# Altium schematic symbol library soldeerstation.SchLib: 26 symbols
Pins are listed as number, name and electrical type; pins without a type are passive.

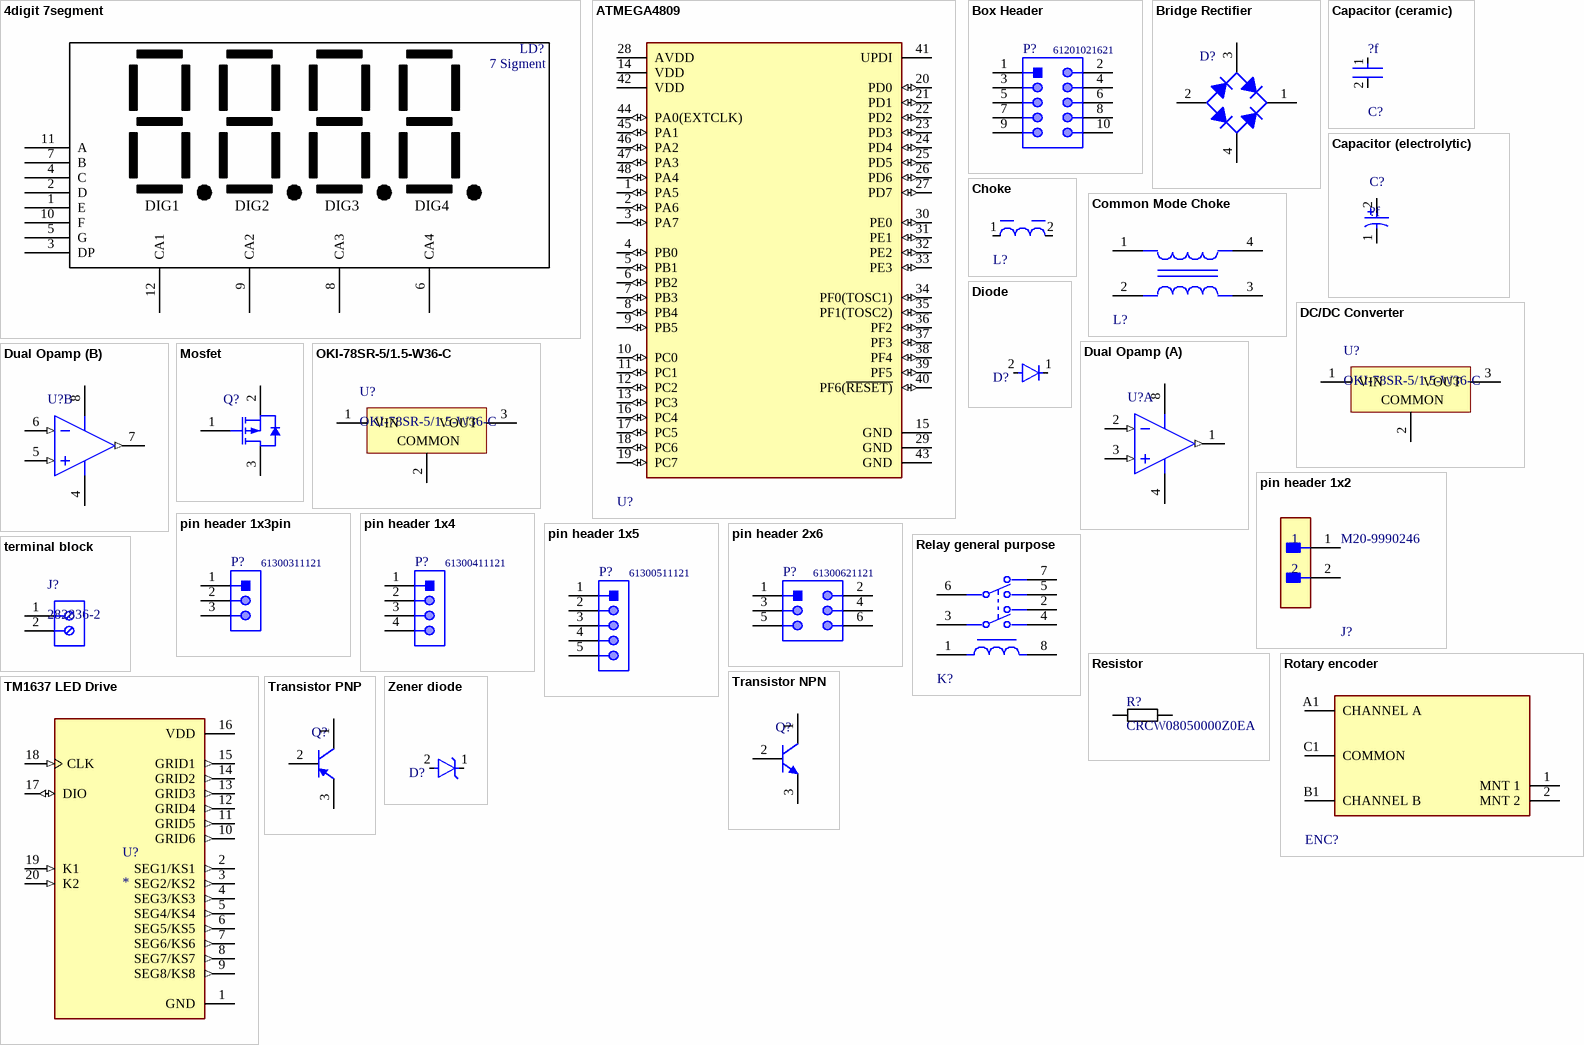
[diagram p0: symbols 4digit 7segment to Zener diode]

## 4digit 7segment
designator LD?, comment 7 Sigment
footprint 7-Segment
pins: 1 E, 2 D, 3 DP, 4 C, 5 G, 6 CA4, 7 B, 8 CA3, 9 CA2, 10 F, 11 A, 12 CA1

## ATMEGA4809
designator U?
Peripherals: Brown-out Detect/Reset; Number of I/Os: 41; Core Architecture: AVR; Memory Size: 48KB; Interface: I2C; Oscillator Type: Internal; Memory Type: FLASH
footprint TQFP_48_L (atmega)
pins: 1 PA5 (io), 2 PA6 (io), 3 PA7 (io), 4 PB0 (io), 5 PB1 (io), 6 PB2 (io), 7 PB3 (io), 8 PB4 (io), 9 PB5 (io), 10 PC0 (io), 11 PC1 (io), 12 PC2 (io), 13 PC3 (io), 14 VDD (power), 15 GND (oe), 16 PC4 (io), 17 PC5 (io), 18 PC6 (io), 19 PC7 (io), 20 PD0 (io), 21 PD1 (io), 22 PD2 (io), 23 PD3 (io), 24 PD4 (io), 25 PD5 (io), 26 PD6 (io), 27 PD7 (io), 28 AVDD (power), 29 GND (power), 30 PE0 (io), 31 PE1 (io), 32 PE2 (io), 33 PE3 (io), 34 PF0(TOSC1) (io), 35 PF1(TOSC2) (io), 36 PF2 (io), 37 PF3 (io), 38 PF4 (io), 39 PF5 (io), 40 PF6(~{RESET)} (io), 41 UPDI, 42 VDD (power), 43 GND (power), 44 PA0(EXTCLK) (io), 45 PA1 (io), 46 PA2 (io), 47 PA3 (io), 48 PA4 (io)

## Box Header
designator P?, comment 61201021621
Male Box Header WR-BHD, THT, Vertical, pitch 2.54 mm, 10 pins; Manufacturer: Wurth Elektronik; Contact Resistance: 20mOhm; Withstanding Voltage: 500VAC; Pin Number: 10; Working Voltage: 250VAC; Pitch: 2.54mm
footprint box header 10-pin (10 pins, straight, gold plating)
pins: 1, 2, 3, 4, 5, 6, 7, 8, 9, 10

## Bridge Rectifier
designator D?
Manufacturer: Diodes Inc; Average Rectified Current-Max: 0.8A; Reverse Voltage-Max [Vrrm]: 600V; Forward Voltage: 1V; Peak Current-Max: 30A; Reverse Current-Max: 5µA; Package Version: 05/2016
footprint ttf (bridge rectifier)
pins: 1 K, 2 A, 3 C, 4 C

## Capacitor (ceramic)
designator C?, comment ?f
Manufacturer: KEMET; Manufacturer Part Number: C0805C224K5RACTU; Value: 0.22 μF; Temperature Characteristic: X7R; Temperature Coefficient: 30ppm/°C; Material: Ceramic; Tolerance: 0.1; Voltage Rating: 50 V
footprint CC_0805_L (choke/capacitor)
pins: 1, 2

## Capacitor (electrolytic)
designator C?, comment ?f
Manufacturer: Panasonic; Voltage Rating: 25 V
footprint CE_D6,3_L4,5 (capacitor electrolytic)
footprint CE_D8_L10
footprint C470µ
pins: 1, 2

## Choke
designator L?
Tolerance: 20%; Shielding: Shielded; Saturation Current: 10A; Test Frequency: 100kHz; RMS Current (Irms): 8.5A; Inductance: 10uH; Series Resistance: 14.1R; DC Resistance (DCR): 14.1mR; Self Resonant Frequency: 18MHz
footprint CC_0805_L (choke/capacitor)
pins: 1, 2

## Common Mode Choke
designator L?
Max Current Rating: 2A; Number of Lines: 2; Impedance: 900R; Element Configuration: Dual; Insulation Resistance: 10MR; Test Frequency: 100MHz; DC Resistance (DCR): 60mR; Voltage Rating (DC): 50V; Current Rating: 2.3A
footprint 2545 (common mode choke)
pins: 1, 2, 3, 4

## DC/DC Converter
designator U?, comment OKI-78SR-5/1.5-W36-C
Manufacturer: Murata; Current - Output (Max): 1.5A; Power (Watts) - Max: 8W; Efficiency: 90.5%; Voltage - Input (Min): 7V; Voltage - Input (Max): 36V; Voltage - Output 1: 5V; Number of Outputs: 1
footprint OKI78SR515W36C ( DC/DC Converter)
pins: 1 VIN (power), 2 COMMON (power), 3 VOUT (power)

## Diode
designator D?
Manufacturer Part Number: 1N4007; Manufacturer: Diotec; Max Surge Forward Current: 27A; Forward Current: 1A; Max Junction Temp: +175°C; Reverse Voltage: 1000V; Value: 15pF; Peak Reverse Current: 5uA
footprint SOD-123FL (diode) (SOD, 2-Leads, Body 2.7x1.65mm)
pins: 1, 2

## Dual Opamp
designator U?
Slew Rate: 0.6V/µs; Supply Current: 100uA; Power Supply Rejection Ratio (PSRR): 86dB; Input Offset Voltage (Vos): 4.5mV; Input Bias Current: 1pA; Amplifier Type: GENERAL PURPOSE; Unity Gain Bandwidth Product: 1MHz; Number of Circuits: 2; Output Current: 23mA; Operating Supply Voltage: 5.5V; Min Supply Voltage: 1.8V; Common Mode Rejection Ratio: 60dB; Voltage Gain: 112dB; Max Supply Voltage: 6V
footprint MSOP_8_L (dual opamp) (TSOP, 8-Leads, Body 3x3mm, Pitch 0.65mm, IPC Low Density)
pins on every part: 4 VSS (power), 8 VDD (power)
part A pins: 1 VOUTA (out), 2 VINA- (in), 3 VINA+ (in)
part B pins: 5 VINB+ (in), 6 VINB- (in), 7 VOUTB (out)

## Mosfet
designator Q?
Manufacturer: Fairchild Semiconductor; Reel Quantity: 3000; Drain Source Voltage Vds: 20V; Power Dissipation Pd: 500mW; On Resistance Rds(on): 52mohm; Full Power Rating Temperature: 25°C; Voltage Vgs Max: -800mV; Pulse Current Idm: 10A; Rds(on) Test Voltage Vgs: -4.5V; External Depth: 2.5mm; Transistor Case Style: SOT-23; No. of Pins: 3; Continuous Drain Current Id: 2.4A; Voltage Vds Typ: -20V; Voltage Vgs th Max: -1.5V; Transistor Polarity: PChannel; Package Version: Rev. 3, 05/2015; External Width: 3.05mm; External Length / Height: 1.12mm; SMD Marking: 304P; SVHC: NoSVHC(19-Dec-2012)
footprint TO_252 (mosfet) (DPAK, 3-Leads, Body 6.5x6.12mm, Pitch 2.28mm, IPC Low Density)
pins: 1 GATE, 2 SOURCE, 3 DRAIN

## OKI-78SR-5/1.5-W36-C
designator U?
Non-Isolated DC/DC Converter; Manufacturer: Murata; Current - Output (Max): 1.5A; Power (Watts) - Max: 8W; Efficiency: 90.5%; Voltage - Input (Min): 7V; Voltage - Input (Max): 36V; Voltage - Output 1: 5V; Number of Outputs: 1
footprint OKI78SR515W36C ( DC/DC Converter)
pins: 1 VIN (power), 2 COMMON (power), 3 VOUT (power)

## pin header 1x2
designator J?, comment M20-9990246
CONN HEADER VERT 2POS 2.54MM; Manufacturer: Harwin; Conn Gender: Male; Conn Orientation: Vertical; Number Of Contacts: 2; Current Rating: 3A
footprint pin header 1x2
pins: 1, 2

## pin header 1x3pin
designator P?, comment 61300311121
THT Vertical Pin Header WR-PHD, Pitch 2.54 mm, Single Row, 3 pins; Manufacturer: Wurth Elektronik; Withstanding Voltage: 500VAC; Working Voltage: 250VAC; Rated Current: 3A; Pitch: 2.54mm; Pin Number: 3; Gender: Male; Contact Resistance: 20mOhm
footprint pin header 1x3 (Pin Header, pitch 2.54 mm, THT, Vertical, single row, 3p)
pins: 1, 2, 3

## pin header 1x4
designator P?, comment 61300411121
THT Vertical Pin Header WR-PHD, Pitch 2.54 mm, Single Row, 4 pins; Manufacturer: Wurth Elektronik; Withstanding Voltage: 500VAC; Rated Current: 3A; Working Voltage: 250VAC; Pin Number: 4; Gender: Male; Contact Resistance: 20mOhm; Pitch: 2.54mm
footprint pin header 1x4 (Pin Header, pitch 2.54 mm, THT, Vertical, single row, 4p)
pins: 1, 2, 3, 4

## pin header 1x5
designator P?, comment 61300511121
THT Vertical Pin Header WR-PHD, Pitch 2.54 mm, Single Row, 5 pins; Manufacturer: Wurth Elektronik; Pin Number: 5; Contact Resistance: 20mOhm; Working Voltage: 250VAC; Pitch: 2.54mm; Withstanding Voltage: 500VAC; Rated Current: 3A; Gender: Male
footprint pin header 1x5 (Pin Header, pitch 2.54 mm, THT, Vertical, single row, 5p)
pins: 1, 2, 3, 4, 5

## pin header 2x6
designator P?, comment 61300621121
THT Vertical Pin Header WR-PHD, Pitch 2.54 mm, Dual Row, 6 pins; Manufacturer: Wurth Elektronik; Contact Resistance: 20mOhm; Withstanding Voltage: 500VAC; Pin Number: 6; Gender: Male; Pitch: 2.54mm; Working Voltage: 250VAC; Rated Current: 3A
footprint pin header 2x6 (Pin Header, pitch 2.54 mm, THT, Vertical, dual row, 6p)
pins: 1, 2, 3, 4, 5, 6

## Relay general purpose
designator K?
Manufacturer Part Number: RT424005; Manufacturer: TE Connectivity; Coil Power: 403mW; Throw Configuration: DPDT; Coil Voltage: 5V; Number Of Contacts: 2; Coil Resistance: 62Ω; Current Rating: 8A; Coil Type: Non-Latching
footprint RT42 (relay general p)
pins: 1 A1, 2 12, 3 11, 4 14, 5 24, 6 21, 7 22, 8 A2

## Resistor
designator R?, comment CRCW08050000Z0EA
Manufacturer: Vishay Dale
footprint R_0805_L (Chip Resistor, 2-Leads, Body 2.00x1.25mm, IPC Low Density)
pins: 1, 2
1 alternate drawing of the same symbol

## Rotary encoder
designator ENC?
Manufacturer Part Number: PEC11R-4015F-N0024; Manufacturer: Bourns; Current Rating: 10mA; Number Of Circuits: 1; Conn Orientation: Vertical; Encoder Type: Incremental; Detent: No; Pulses Per Rev: 24; Voltage Rating Dc: 5V
footprint PEC11R4225FN0024 (rotary enc)
pins: 1 MNT 1, 2 MNT 2, A1 CHANNEL A, B1 CHANNEL B, C1 COMMON

## terminal block
designator J?, comment 282836-2
Female Header, Pitch 5 mm, 1 x 2 Position, Height 10 mm, Tail Length 3.5 mm, Rohs, Bulk; Manufacturer: TE Connectivity; Wire Gauge: 16-30AWG; Product Training Modules: Wire-to-BoardEurostyleTerminalBlocks; Clamp Material - Plating: Brass-NickelPlated; Voltage: 300V; Mating Orientation: HorizontalwithBoard; Current: 13.5A; Pitch: 0.197"(5.00mm); Screw Thread: M3; 3D Model: 282836-2.pdf; Other Names: 5ULV-02B / A98076; Dynamic Catalog: BuchananSeries; Number of Levels: 1; Torque - Screw: 0.68Nm(6Lb-In); Featured Product: EurostyleTerminalBlockConnectors; Positions Per Level: 2; Wire Termination: Screw-RisingCageClamp
footprint terminal_block (Female Header, Pitch 5mm, 1 x 2 Position, Height 10mm)
pins: 1, 2

## TM1637 LED Drive
designator U?
MF: Titan Micro Electronics; MP: TM1637
footprint SOP_20_L (led driver) (SOIC,20-Leads,Body 12.9x5.6mm,Pitch 1.27mm,IPC Low Density)
pins: 1 GND (power), 2 SEG1/KS1 (out), 3 SEG2/KS2 (out), 4 SEG3/KS3 (out), 5 SEG4/KS4 (out), 6 SEG5/KS5 (out), 7 SEG6/KS6 (out), 8 SEG7/KS7 (out), 9 SEG8/KS8 (out), 10 GRID6 (out), 11 GRID5 (out), 12 GRID4 (out), 13 GRID3 (out), 14 GRID2 (out), 15 GRID1 (out), 16 VDD (power), 17 DIO (io), 18 CLK (in), 19 K1 (in), 20 K2 (in)

## Transistor NPN
designator Q?
Manufacturer: On Semiconductor; PartNumber: BC547C; IC Continuous (A): 0.1; fT Min (MHz): 150; Packing: Bulk Box; Polarity: NPN
footprint SOT_23 (transistors) (SOT23, 3-Leads, Body 2.92x1.3mm, Pitch 0.95mm)
pins: 1 C, 2 B, 3 E

## Transistor PNP
designator Q?
Manufacturer: On Semiconductor; PartNumber: BC557C; Polarity: PNP; IC Continuous (A): -0.1; Packing: Bulk Box
footprint SOT_23 (transistors) (SOT23, 3-Leads, Body 2.92x1.3mm, Pitch 0.95mm)
pins: 1 C, 2 B, 3 E

## Zener diode
designator D?
Manufacturer Part Number: 1N4007; Manufacturer: Diotec; Max Surge Forward Current: 27A; Forward Current: 1A; Max Junction Temp: +175°C; Reverse Voltage: 1000V; Value: 15pF; Peak Reverse Current: 5uA
footprint SOD-123FL (diode) (SOD, 2-Leads, Body 2.7x1.65mm)
pins: 1, 2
